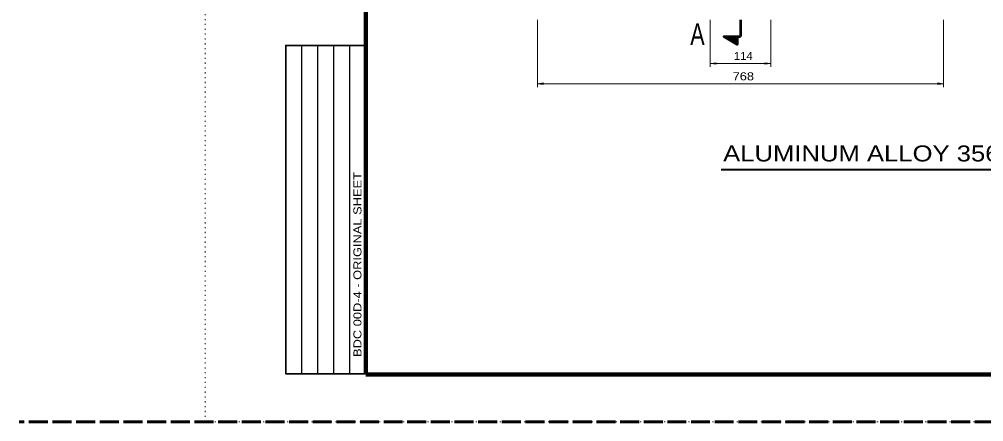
# Model space of a CAD drawing. Extents: x 312583 to 312854, y 144419 to 144597.
# Drawn here: x 312583.5 to 312675.3, y 144418.6 to 144456.8 of the extents above; entities that cross this region are included whole.
import ezdxf
from ezdxf.enums import TextEntityAlignment as Align

# ---------------------------------------------------------------- set-up
doc = ezdxf.new("R2010")
doc.units = 0
doc.header["$LTSCALE"] = 0.3
doc.linetypes.add('DOTTED', pattern=[1.5, 0.3, -1.2])
doc.linetypes.add('LONG_DASHED', pattern=[7.5, 6, -1.5])
for name, color, linetype, lineweight in [('1', 7, 'Continuous', 25), ('2', 7, 'Continuous', 13), ('63', 7, 'DOTTED', 13)]:
    doc.layers.add(name, color=color, linetype=linetype, lineweight=lineweight)

msp = doc.modelspace()

# ---------------------------------------------------------------- linework, layer by layer
at = {"layer": '1', "linetype": 'DOTTED', "lineweight": 13}
msp.add_line((312601.2, 144418.5846), (312601.2, 144596.7846), dxfattribs=at)
at = {"layer": '1'}
for p, q in [((312610.4087, 144423.1446), (312610.4087, 144454.3629)), ((312611.9315, 144423.1446), (312611.9315, 144454.3629)), ((312613.4543, 144423.1446), (312613.4543, 144454.3629)), ((312614.9772, 144423.1446), (312614.9772, 144454.3629))]:
    msp.add_line(p, q, dxfattribs=at)
at = {"layer": '1', "lineweight": 158}
msp.add_line((312616.5, 144423.0846), (312849, 144423.0846), dxfattribs=at)
at = {"layer": '1', "linetype": 'LONG_DASHED', "lineweight": 60}
msp.add_line((312851.75, 144418.5846), (312583.526, 144418.5846), dxfattribs=at)
at = {"layer": '1', "lineweight": 158}
msp.add_lwpolyline([(312616.5, 144423.1446), (312616.5, 144585.0846), (312849, 144585.0846)], dxfattribs=at)
at = {"layer": '1', "lineweight": 35}
msp.add_lwpolyline([(312616.5, 144423.1446), (312608.8858, 144423.1446), (312608.8858, 144454.3629), (312616.5, 144454.3629)], dxfattribs=at)
at = {"layer": '2'}
for p, q in [((312632.8294, 144456.789), (312632.8294, 144450.4027)), ((312649.2821, 144456.789), (312649.2821, 144452.3193)), ((312655.0321, 144456.789), (312655.0321, 144452.3193)), ((312671.4771, 144456.789), (312671.4771, 144450.4027)), ((312649.2821, 144452.6413), (312649.8571, 144452.7103)), ((312649.2821, 144452.6413), (312655.0321, 144452.6413)), ((312649.2821, 144452.6413), (312649.8571, 144452.5647)), ((312649.8571, 144452.7103), (312649.6731, 144452.6413)), ((312649.8571, 144452.5647), (312649.6731, 144452.6413)), ((312654.4494, 144452.7103), (312654.6334, 144452.6413)), ((312655.0321, 144452.6413), (312654.4494, 144452.7103)), ((312654.4494, 144452.5647), (312654.6334, 144452.6413)), ((312655.0321, 144452.6413), (312654.4494, 144452.5647)), ((312632.8294, 144450.7247), (312633.4044, 144450.7937)), ((312632.8294, 144450.7247), (312671.4771, 144450.7247)), ((312632.8294, 144450.7247), (312633.4044, 144450.648)), ((312633.4044, 144450.7937), (312633.2204, 144450.7247)), ((312633.4044, 144450.648), (312633.2204, 144450.7247)), ((312670.9021, 144450.7937), (312671.0861, 144450.7247)), ((312671.4771, 144450.7247), (312670.9021, 144450.7937)), ((312670.9021, 144450.648), (312671.0861, 144450.7247)), ((312671.4771, 144450.7247), (312670.9021, 144450.648))]:
    msp.add_line(p, q, dxfattribs=at)
at = {"layer": '2', "lineweight": 53}
for p in [(312652.1571, 144456.789), (312651.8351, 144455.1943)]:
    msp.add_line(p, (312652.1571, 144455.1943), dxfattribs=at)
at = {"layer": '2', "lineweight": 35}
for p, q in [((312650.5701, 144455.1943), (312650.5701, 144455.1867)), ((312650.5931, 144455.1943), (312650.5854, 144455.179)), ((312650.6084, 144455.1943), (312650.5931, 144455.1713)), ((312650.6238, 144455.1943), (312650.6084, 144455.1637)), ((312650.6468, 144455.1943), (312650.6238, 144455.156)), ((312650.6621, 144455.1943), (312650.6391, 144455.1483)), ((312650.6851, 144455.1943), (312650.6544, 144455.1407)), ((312650.7004, 144455.1943), (312650.6698, 144455.133)), ((312650.7234, 144455.1943), (312650.6774, 144455.1253)), ((312650.7388, 144455.1943), (312650.6928, 144455.1177)), ((312650.7541, 144455.1943), (312650.7081, 144455.11)), ((312650.7771, 144455.1943), (312650.7234, 144455.1023)), ((312650.7924, 144455.1943), (312650.7311, 144455.0947)), ((312650.8078, 144455.1943), (312650.7464, 144455.087)), ((312650.8308, 144455.1943), (312650.7618, 144455.0793)), ((312650.8538, 144455.1943), (312650.7771, 144455.0717)), ((312650.8691, 144455.1943), (312650.7924, 144455.0563)), ((312650.8844, 144455.1943), (312650.8078, 144455.0563)), ((312650.8998, 144455.1943), (312650.8154, 144455.041)), ((312650.9228, 144455.1943), (312650.8308, 144455.041)), ((312650.9458, 144455.1943), (312650.8461, 144455.0257)), ((312650.9611, 144455.1943), (312650.8538, 144455.0257)), ((312650.9764, 144455.1943), (312650.8768, 144455.0103)), ((312650.9918, 144455.1943), (312650.8844, 144455.0103)), ((312651.0148, 144455.1943), (312650.8998, 144454.995)), ((312651.0378, 144455.1943), (312650.9151, 144454.995)), ((312651.0531, 144455.1943), (312650.9304, 144454.9797)), ((312651.0684, 144455.1943), (312650.9458, 144454.9797)), ((312651.0838, 144455.1943), (312650.9611, 144454.9643)), ((312651.1068, 144455.1943), (312650.9688, 144454.9567)), ((312651.1221, 144455.1943), (312650.9841, 144454.949)), ((312651.1451, 144455.1943), (312650.9994, 144454.9413)), ((312651.1604, 144455.1943), (312651.0071, 144454.9337)), ((312651.1834, 144455.1943), (312651.0224, 144454.926)), ((312651.1988, 144455.1943), (312651.0378, 144454.9183)), ((312651.2141, 144455.1943), (312651.0531, 144454.9107)), ((312651.2371, 144455.1943), (312651.0684, 144454.903)), ((312651.2524, 144455.1943), (312651.0838, 144454.8953)), ((312651.2678, 144455.1943), (312651.0991, 144454.8877)), ((312651.2908, 144455.1943), (312651.1068, 144454.88)), ((312651.3138, 144455.1943), (312651.1221, 144454.8723)), ((312651.3291, 144455.1943), (312651.1374, 144454.8647)), ((312651.3444, 144455.1943), (312651.1451, 144454.857)), ((312651.3674, 144455.1943), (312651.1604, 144454.8493)), ((312651.3828, 144455.1943), (312651.1758, 144454.8417)), ((312651.4058, 144455.1943), (312651.1911, 144454.8263)), ((312651.4211, 144455.1943), (312651.2064, 144454.8263)), ((312651.4364, 144455.1943), (312651.2218, 144454.811)), ((312651.4518, 144455.1943), (312651.2371, 144454.811)), ((312651.4748, 144455.1943), (312651.2524, 144454.7957)), ((312651.4978, 144455.1943), (312651.2601, 144454.7957)), ((312651.5131, 144455.1943), (312651.2754, 144454.7803)), ((312651.5284, 144455.1943), (312651.2908, 144454.7803)), ((312651.5438, 144455.1943), (312651.2984, 144454.765)), ((312651.5668, 144455.1943), (312651.3138, 144454.765)), ((312651.5898, 144455.1943), (312651.3291, 144454.7497)), ((312651.6051, 144455.1943), (312651.3444, 144454.7497)), ((312651.6204, 144455.1943), (312651.3598, 144454.7343)), ((312651.6434, 144455.1943), (312651.3751, 144454.7267)), ((312651.6588, 144455.1943), (312651.3904, 144454.719)), ((312651.6818, 144455.1943), (312651.3981, 144454.7113)), ((312651.6971, 144455.1943), (312651.4134, 144454.7037)), ((312651.7124, 144455.1943), (312651.4288, 144454.696)), ((312651.7354, 144455.1943), (312651.4364, 144454.6883)), ((312651.7508, 144455.1943), (312651.4518, 144454.6807)), ((312651.7738, 144455.1943), (312651.4671, 144454.673)), ((312651.7891, 144455.1943), (312651.4824, 144454.6653)), ((312651.8044, 144455.1943), (312651.4978, 144454.6577)), ((312651.8274, 144455.1943), (312651.5131, 144454.65)), ((312651.8351, 144455.179), (312651.5208, 144454.6423)), ((312651.8351, 144455.1483), (312651.5438, 144454.6347)), ((312651.8351, 144455.1177), (312651.5514, 144454.627)), ((312651.8351, 144455.087), (312651.5668, 144454.6193)), ((312651.8351, 144455.0563), (312651.5821, 144454.6117)), ((312651.8351, 144455.0257), (312651.5898, 144454.5963)), ((312651.8351, 144454.995), (312651.6051, 144454.5963)), ((312651.8351, 144454.9567), (312651.6204, 144454.581)), ((312651.8351, 144454.926), (312651.6358, 144454.5733)), ((312651.8351, 144454.8953), (312651.6511, 144454.5657)), ((312651.8351, 144454.857), (312651.6588, 144454.558)), ((312651.8351, 144454.8263), (312651.6741, 144454.5503)), ((312651.8351, 144454.7957), (312651.6894, 144454.5427)), ((312651.8351, 144454.765), (312651.6971, 144454.535)), ((312651.8351, 144454.7343), (312651.7201, 144454.5273)), ((312651.8351, 144454.7037), (312651.7278, 144454.5197)), ((312651.8351, 144454.673), (312651.7431, 144454.512)), ((312651.8351, 144454.6347), (312651.7584, 144454.5043)), ((312651.8351, 144454.6117), (312651.7738, 144454.4967)), ((312651.8351, 144454.5733), (312651.7891, 144454.489)), ((312651.8351, 144454.5427), (312651.8044, 144454.4813)), ((312651.8351, 144454.5043), (312651.8121, 144454.4737)), ((312651.8351, 144454.4737), (312651.8274, 144454.466))]:
    msp.add_line(p, q, dxfattribs=at)
at = {"layer": '2', "lineweight": 40}
msp.add_line((312650.3168, 144442.552), (312688.0105, 144442.552), dxfattribs=at)
at = {"layer": '2', "lineweight": 53}
msp.add_lwpolyline([(312651.8351, 144455.1943), (312651.8351, 144454.4583), (312650.5624, 144455.1943)], close=True, dxfattribs=at)
at = {"layer": '63'}
msp.add_lwpolyline([(312601.2, 144418.5846), (312853.5, 144418.5846), (312853.5, 144596.7846)], dxfattribs=at)

# ---------------------------------------------------------------- texts
at = {"layer": '1', "width": 1.2}
msp.add_text('BDC 00D-4 - ORIGINAL SHEET', height=0.7614, rotation=90, dxfattribs=at).set_placement((312616.0832, 144424.7374))
at = {"layer": '2'}
for s, height, width, p in [('A', 2.044, 0.75, (312648.0592, 144454.4047)), ('114 ', 0.76, 1.05, (312652.5687, 144452.9804)), ('768 ', 0.76, 1.2, (312652.5951, 144451.0473)), ('ALUMINUM ALLOY 356 AS CAST', 1.52, 1.2, (312669.2089, 144443.3309))]:
    msp.add_text(s, height=height, dxfattribs=dict(at, width=width)).set_placement(p, align=Align.CENTER)

doc.saveas('drawing.dxf')
